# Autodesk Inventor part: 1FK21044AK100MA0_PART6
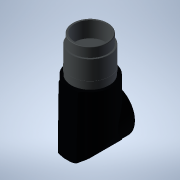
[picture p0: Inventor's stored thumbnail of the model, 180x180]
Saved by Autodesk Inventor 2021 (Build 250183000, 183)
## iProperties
Created: 2025-04
Part Number: 1FK21044AK100MA0_PART6
Material: Generic
Catalog Web Link: www.3dfindit.com
Description: -Servo synchronous motor
Document SubType Name: Modeling
Designer: psAdmin
Mass: 11.0817 g
Surface Area: 35.706 cm^2
Volume: 11.0817 cm^3
Density: 1 g/cm^3
Appearance: PSOLRGB-176-176-176
Category: PARTsolutions
Title: 1FK21044AK100MA0_PART6
Author: Cadenas PARTsolutions
Comments: Servo synchronous motor
Sending System: PARTsolutions
Preprocessor: ST-DEVELOPER v19.3
PSOL_IDENT_0: {$CADENAS_DATA/23d-libs/siemens_ag/_cat_/5e/d8/1fk21044ak100ma0.prj},213 {VTYP=3D},{NB=1FK21044AK100
PSOL_IDENT_1: MA0_PART6},{LINA=1FK21044AK100MA0_PART6},{NN=1FK21044AK100MA0_PART6},{NOPRJ=TRUE},{DATE=19.08.2025 1
PSOL_IDENT_2: 4:00:41},{GEOMDATE=30.07.2025 02:00:53},{VERSION=},{LINEID=10},{WBVAR=},{WBNUMERIC=}  {NB=1FK21044AK
PSOL_IDENT_3: 100MA0_PART6},{LINA=1FK21044AK100MA0_PART6},{KT=DUMMY},{PREVIEW=../../../_pool_/cb/72/p_d211_xx_0043
PSOL_IDENT_4: 4j.png},{DESCSHORT=SIMOTICS S-1FK2 HD, SINAMICS S210 3AC 400V-480V, 0.95 Nm, 6000 rpm},{DESCLONG=SIM
PSOL_IDENT_5: OTICS S-1FK2 HD servo motor M0=1.27 Nm; PN = 0.6 kW at nN=6000 rpm (380-480 V); PN = 0.4 kW at nN=30
PSOL_IDENT_6: 00 rpm (200-240 V); with holding brake; degree of protection IP64; cylindrical shaft D19x40mm; absol
PSOL_IDENT_7: ute encoder 22-bit + 12-bit multiturn (encoder AM22DQC); with OCC interface; plug size M17, rotatabl
PSOL_IDENT_8: e; SIMOTICS S-1FK2 servomotorfor a wide range of uses in industrial environments. SIMOTICS S‑1FK2 se
PSOL_IDENT_9: rvomotors are compact synchronous motors with a high dynamic performance that set themselves apart a
PSOL_IDENT_10: s a result of their high power density, degree of protection and overload capability. The motors are
PSOL_IDENT_11: available in two variants: as High Dynamic variant (highest dynamic performance as a result of the
PSOL_IDENT_12: low intrinsic moment of inertia for applications demanding a high dynamic performance with low moved
PSOL_IDENT_13: masses) - and as Compact variant (precise and stable closed-loop control for medium up to large mov
PSOL_IDENT_14: ed masses as a result of a medium intrinsic moment of inertia). SIMOTICSS‑1FK2 servomotors fully exp
PSOL_IDENT_15: loit their strengths in a system with the SINAMICSS210 frequency converter and simple connection usi
PSOL_IDENT_16: ng the one cable connection (OCC). Advantages include the short control and positioning times, fast
PSOL_IDENT_17: and precise correction of disturbing quantities as well as stable control with a high dynamic perfor
PSOL_IDENT_18: mance. The servo motors can be configured to address a wide range of requirements. For example with
PSOL_IDENT_19: and without holding brake, IP64 or IP65 degree of protection, singleturn or multiturn absolute encod
PSOL_IDENT_20: ers - to name just a few. Further, the servomotors are available in different shaft heights extendin
PSOL_IDENT_21: g from 20 to 100. A shaft sealing ring is available to achieve an IP65 degree of protection and for
PSOL_IDENT_22: subsequent mounting at the motor or as spare part. SIMOTICS - the optimum motor for each and every m
PSOL_IDENT_23: otion control application.},{INTNO=804766910005},{SUPPLIERALTNO=1FK2104-4AK10-0MA0},{MANUID=1FK21044
PSOL_IDENT_24: AK100MA0},{MANUNAME=Siemens},{MANUTYPEDESC=Synchronous motor 1FK2-HD 1,27 Nm},{AAU732=SIMOTICS},{AAO
PSOL_IDENT_25: 057=S-1FK2},{AAU734=SIMOTICS S-1FK2 HD servo motor M0=1.27 Nm; PN = 0.6 kW at nN=6000 rpm (380-480 V
PSOL_IDENT_26: ); PN = 0.4 kW at nN=3000 rpm (200-240 V); with holding brake; degree of protection IP64; cylindrica
PSOL_IDENT_27: l shaft D19x40mm; absolute encoder 22-bit + 12-bit multiturn (encoder AM22DQC); with OCC interface;
PSOL_IDENT_28: plug size M17, rotatable;},{AAW338=Synchronous motor 1FK2-HD 1,27 Nm},{AAO742=SIMOTICS},{AAO663=4042
PSOL_IDENT_29: 948691076},{NOCUPEROU=1},{PRICEQUANTITY=1},{QUANTITYMIN=1},{QUANTITYINT=1},{CTN=85015100},{COO=DE},{
PSOL_IDENT_30: AAO676=1FK2104-4AK10-0MA0},{AAO677=Siemens AG},{ORDERUNIT=C62},{CONTENTUNIT=C62}
NB: 1FK21044AK100MA0_PART6
NT: Servo synchronous motor
NBSYN: $MANUID._PART6
LINA: 1FK21044AK100MA0_PART6
CATALOG: SIEMENS
PREVIEW: ../../../_pool_/cb/72/p_d211_xx_00434j.png
DESCSHORT: SIMOTICS S-1FK2 HD, SINAMICS S210 3AC 400V-480V, 0.95 Nm, 6000 rpm
DESCLONG: SIMOTICS S-1FK2 HD servo motor M0=1.27 Nm; PN = 0.6 kW at nN=6000 rpm (380-480 V); PN = 0.4 kW at nN=3000 rpm (200-240 V); with holding brake; degree of protect
INTNO: 804766910005
SUPPLIERALTNO: 1FK2104-4AK10-0MA0
MANUID: 1FK21044AK100MA0
MANUNAME: Siemens
MANUTYPEDESC: Synchronous motor 1FK2-HD 1,27 Nm
AAU732: SIMOTICS
AAO057: S-1FK2
AAU734: SIMOTICS S-1FK2 HD servo motor M0=1.27 Nm; PN = 0.6 kW at nN=6000 rpm (380-480 V); PN = 0.4 kW at nN=3000 rpm (200-240 V); with holding brake; degree of protect
AAW338: Synchronous motor 1FK2-HD 1,27 Nm
AAO742: SIMOTICS
AAO663: 4042948691076.0
NOCUPEROU: 1
PRICEQUANTITY: 1
QUANTITYMIN: 1
QUANTITYINT: 1
CTN: 85015100
COO: DE
ARTICLENO: 1FK21044AK100MA0_PART6
BOMINFO: 1FK21044AK100MA0_PART6
CREATOR: CADENAS GmbH
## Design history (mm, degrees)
feature "2025_04_17_15_35_41_0937"
body "Solid1"
